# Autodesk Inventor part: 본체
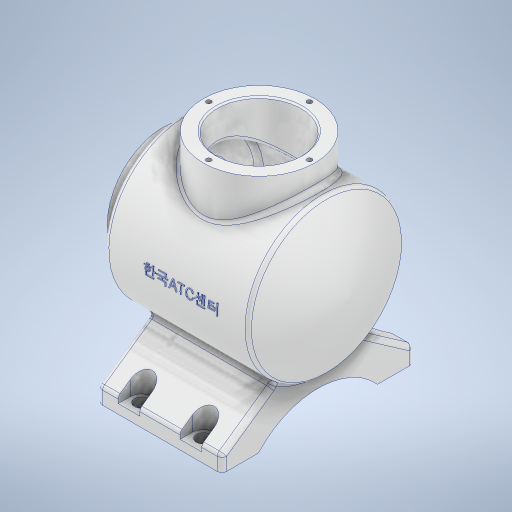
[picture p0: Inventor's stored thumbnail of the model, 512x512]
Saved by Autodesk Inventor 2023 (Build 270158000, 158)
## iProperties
Created: 2023-12
Part Number: 본체
Material: 알루미늄 6061
Document SubType Name: Modeling
Designer: asung
Density: 2.7 g/cm^3
Appearance: 알루미늄 - 평지
Mass: 1280.21 g
Surface Area: 1042.78 cm^2
Volume: 474.153 cm^3
Author: asung
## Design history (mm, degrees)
sketch "스케치1"
  geometry: L1 (0, 0)-(120, 0); L2 (0, 0)-(0, -36); L3 (0, -36)-(12, -36); L4 (12, -36)-(12, -50); L5 (12, -50)-(104.642, -50); A1 r 113 centre (7.235, 7.279) between (104.642, -50) and (120, 0)
  constraints: 10 end point, 3 perpendicular, 2 point on circle, 1 centre point, 1 horizontal, 1 vertical
  dimensions: "d0" = 120 distance of L1.end L1.start; "d1" = 113 radius of A1; "d2" = 72 diameter of L3 L1; "d3" = 100 diameter of L5 L1; "d5" = 108 distance from line of L1.end L4; "d6" = 14.5578 diameter of A1.centre L1
revolve "회전1" sketch "스케치1" stored, may be unused: angle "d7" = 90 deg
sketch "스케치2"
  geometry: L1 (0, 36)-(0, -36) reference; L2 (0, -36)-(-12, -36) reference; L3 (-12, -36)-(-12, -50) reference; L4 (-12, -50)-(-104.642, -50) reference; L5 (-104.642, 50)-(-12, 50) reference; L6 (-12, 50)-(-12, 36) reference; L7 (-12, 36)-(0, 36) reference; L8 (0, 0)-(-120, 0); L9 (0, 0)-(0, 27); L10 (0, 27)-(-19, 27); L11 (-19, 27)-(-19, 40); L12 (-22, 43)-(-98.743, 43); A1 r 113 centre (-7.235, 7.279) between (-120, 0) and (-104.642, -50) reference; A2 r 113 centre (-7.235, -7.279) between (-104.642, 50) and (-120, 0) reference; A3 r 106 centre (-7.235, -7.279) between (-101.408, 41.377) and (-112.984, 0); A4 r 3 centre (-22, 40) between (-19, 40) and (-22, 43); A5 r 3 centre (-98.743, 40) between (-98.743, 43) and (-101.408, 41.377); 2 further points
  constraints: 10 end point, 8 point on circle, 4 tangent, 3 centre point, 3 point on line, 1 equal radius, 1 horizontal, 1 midpoint, 1 parallel, 1 perpendicular
  dimensions: "d8" = 7 radial gap between concentric circles of A2 A3; "d9" = 54 diameter of L10 L8; "d10" = 19 distance of L10.end L9.end; "d11" = 7 distance between parallel lines of L5 L12; "d12" = 7 distance from line of point (-12, 43) L11 (derived); "d13" = 3 radius of A4
revolve "회전2" sketch "스케치2" stored, may be unused: angle "d14" = 90 deg
node "작업 평면1"
sketch "스케치3"
  geometry: L1 (-104.642, 50)-(-104.642, -50) reference; L2 (-12, 50)-(-12, -50) reference; L3 (0, 0)-(-62, 0); C1 r 36 at (-62, 0)
  constraints: 2 end point, 1 centre point, 1 coincident, 1 horizontal
  dimensions: "d18" = 62 distance of L3.start L3.end; "d19" = 72 diameter of C1
extrude "돌출1" join sketch "스케치3" stored distance "d20" = 10; taper "d21" = 0 deg
sketch "스케치4"
  geometry: C1 r 36 at (0, 0) reference; C2 r 27 at (0, 0); 1 further point
  constraints: 1 centre point, 1 coincident
  dimensions: "d22" = 54 diameter of C2
extrude "돌출2" cut sketch "스케치4" stored distance "d23" = 10; taper "d24" = 0 deg
chamfer "모따기1" distance "d25" = 1; stored, may be unused: second distance "d26" = 2, angle "d27" = 45 deg
fillet "모깎기1" dims "d28" = 3
fillet "모깎기2" dims "d29" = 3
sketch "스케치5" dims "d30" = 65
  geometry: C1 r 36 at (0, 0) reference; C2 r 28 at (0, 0) reference; 3 further points
  constraints: 1 coincident, 1 vertical alignment, 2 other
hole "구멍1" sketch "스케치5" at (0, 32.5) diameter "d31" = 3.242; stored, may be unused: countersink angle "d35" = 90 deg, drill point angle "d37" = 118 deg; dims "d32" = 8, "d33" = 4, "d34" = 2, "d36" = 10
sketch "스케치6" dims "d41" = 65
  geometry: C1 r 36 at (0, 0) reference; C2 r 28 at (0, 0) reference; 3 further points
  constraints: 1 coincident, 1 vertical alignment, 2 other
hole "구멍2" sketch "스케치6" at (0, 32.5) diameter "d42" = 3.242; stored, may be unused: countersink angle "d46" = 90 deg, drill point angle "d48" = 118 deg; dims "d43" = 8, "d44" = 4, "d45" = 2, "d47" = 10
node "작업 평면2"
sketch "스케치7"
  geometry: L1 (-62, -67)-(-62, -77); L2 (-62, -77)-(-38.5, -77); L3 (26.694, -42.278)-(62, -67); L4 (62, -67)-(62, -77); L5 (62, -77)-(38.5, -77); L6 (-62, -67)-(-26.694, -42.278); C1 r 42.236 at (0, 0) reference; A1 r 50 centre (0, 0) between (26.694, -42.278) and (-26.694, -42.278) reference; A2 r 52.096 centre (0, -112.096) between (38.5, -77) and (-38.5, -77); 5 further points
  constraints: 12 end point, 5 point on circle, 2 coincident, 2 midpoint, 2 perpendicular, 2 point on line, 1 centre point, 1 collinear, 1 vertical, 1 vertical alignment
  dimensions: "d56" = 10 distance of L3.end L4.end; "d57" = 10 distance of L1.start L1.end; "d60" = 17 vertical distance of L2.end point (0, -60); "d61" = 77 distance of L5.end L2.end; "d62" = 55 deg angle of L3 L4; "d63" = 55 deg angle of L6 L1; "d75" = 124 distance of point (-62, -72) point (62, -72); "d101" = 77 distance from line of L2 point (0, 0)
extrude "돌출3" join sketch "스케치7" distance "d64" = 80; taper "d65" = 0 deg
node "작업 평면3"
sketch "스케치10"
  geometry: L1 (100, -42.278)-(20, -42.278) reference; L2 (20, -42.278)-(20, -42.278) reference; L3 (20, -42.278)-(100, -42.278) reference; L4 (100, -42.278)-(100, -42.278) reference; L5 (15, 50)-(15, -50) reference; L6 (102.91, -50)-(102.91, 50) reference; L7 (0, -36)-(0, 36) reference; L8 (12, -47)-(12, 47) reference; L9 (9, -36)-(9, 36) reference; L10 (15, 50)-(102.91, 50) reference; A1 r 113 centre (7.235, -7.279) between (120, 0) and (105.52, 48.48) reference; A2 r 10.263 centre (7.235, -7.279) between (0, 0) and (0, 0) reference; A3 r 10.263 centre (7.235, -7.279) between (0, 0) and (0, 0) reference; A4 r 113 centre (7.235, 7.279) between (105.52, -48.48) and (120, 0) reference; 3 further points
  constraints: 1 vertical alignment, 1 other
  dimensions: "d74" = 62 distance from line of point (62, 1.607) L7 (derived)
feature "엠보싱1" sketch "스케치10" dims "d0" = 120, "d1" = 113, "d2" = 72, "d3" = 100, "d5" = 108, "d6" = 14.5578, "d8" = 7, "d9" = 54, "d10" = 19, "d11" = 7, "d12" = 7 (derived), "d13" = 3, "d76" = 0.5, "d77" = 0
sketch "스케치11" dims "d80" = 9, "d82" = 9
  geometry: L1 (80, 23.5)-(80, 0) reference; L2 (80, 0)-(0, 0) reference; L3 (0, 0)-(0, 23.5) reference; L4 (0, -100.5)-(0, -77) reference; L5 (0, -77)-(80, -77) reference; L6 (80, -77)-(80, -100.5) reference; L7 (80, 0)-(80, -77) reference; L8 (0, -77)-(0, 0) reference; L9 (40, 23.5)-(40, -100.5); L10 (80, -38.5)-(0, -38.5); L11 (55.5, 15.5)-(24.5, 15.5); L12 (24.5, -92.5)-(55.5, -92.5); L13 (60, 15.5)-(20, -92.5); L14 (20, 15.5)-(60, -92.5); L15 (20, 11)-(20, -38.5); L16 (20, -77)-(20, -88); L17 (0, 23.5)-(80, 23.5) reference; L18 (80, -100.5)-(0, -100.5) reference; A1 r 4.5 centre (20, 15.5) between (24.5, 15.5) and (20, 11); A2 r 4.5 centre (20, -92.5) between (20, -88) and (24.5, -92.5); 4 further points
  constraints: 16 end point, 5 midpoint, 4 coincident, 4 point on circle, 2 centre point, 2 horizontal alignment, 2 perpendicular, 2 point on line, 1 horizontal, 1 parallel, 4 other
  dimensions: "d79" = 108 distance of L13.end L14.start; "d81" = 9 diameter of A1; "d83" = 9 diameter of A2
extrude "돌출4" cut sketch "스케치11" distance "d84" = 30; taper "d85" = 0 deg
node "작업 평면4"
sketch "스케치12" dims "d90" = 14
  geometry: L1 (80, -6.483)-(0, -6.483) reference; L2 (0, -70.517)-(80, -70.517) reference; L3 (13, 15.5)-(13, 29.361); L4 (13, 29.361)-(27, 29.361); L5 (27, 29.361)-(27, 15.5); L6 (67, 15.5)-(53, 15.5); L7 (53, 15.5)-(53, 31.728); L8 (53, 31.728)-(67, 31.728); L9 (67, 31.728)-(67, 15.5); L10 (80, 23.5)-(80, -6.483) reference; L11 (0, -6.483)-(0, 23.5) reference; L12 (0, 23.5)-(80, 23.5) reference; L13 (80, -100.5)-(0, -100.5) reference; L14 (0, -100.5)-(0, -70.517) reference; L15 (80, -70.517)-(80, -100.5) reference; C1 r 4.5 at (20, -92.5) reference; C2 r 4.5 at (20, 15.5) reference; C3 r 4.5 at (60, -92.5) reference; C4 r 4.5 at (60, 15.5) reference; 5 further points
  constraints: 14 end point, 3 parallel, 2 coincident, 1 horizontal, 1 perpendicular, 6 other
extrude "돌출5" cut sketch "스케치12" distance "d91" = 30; taper "d92" = 0 deg
fillet "모깎기5" dims "d93" = 3
fillet "모깎기10" dims "d98" = 3
fillet "모깎기11" dims "d99" = 3
fillet "모깎기12" dims "d100" = 3
node "솔리드1"
pattern_circular "원형 패턴1" dims angle "d39" = 360 deg
pattern_circular "원형 패턴2" dims angle "d50" = 360 deg
mirror "미러1"
node "투영된 루프1"
node "투영된 루프2"
node "투영된 루프3"
node "투영된 루프4"
node "투영된 루프6"
node "절단 모서리 투영1"
node "절단 모서리 투영2"
node "절단 모서리 투영5"
node "절단 모서리 투영6"
feature "A9D066F2-1C7D-4E18-AEED-F7BC21143FA4" dims "d31" = 3.242, "d32" = 8, "d33" = 4, "d34" = 2, "d35" = 90 deg, "d36" = 10, "d37" = 118 deg
other parameters: "d15" = 65, "d86" = -6
